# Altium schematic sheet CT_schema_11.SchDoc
size 281 x 153 mm
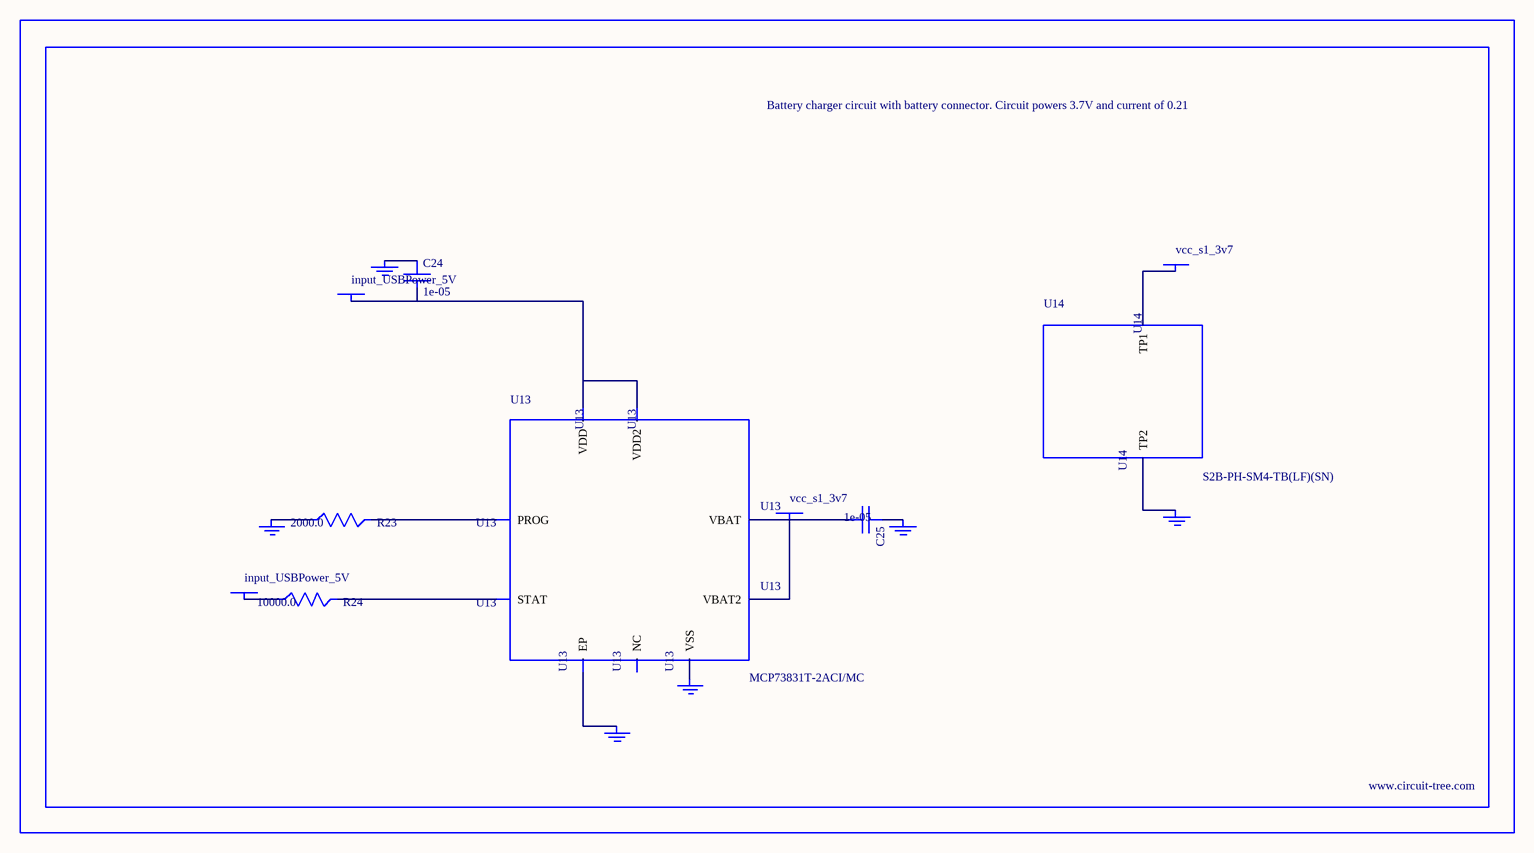
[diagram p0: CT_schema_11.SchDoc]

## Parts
BORDER10  (no value)
C24  1e-05  [C1206]
C25  1e-05  [C1206]
GND_INSTANCE_10_0  (no value)
GND_INSTANCE_10_1  (no value)
GND_INSTANCE_10_2  (no value)
GND_INSTANCE_10_3  (no value)
GND_INSTANCE_10_4  (no value)
GND_INSTANCE_10_5  (no value)
POWER_INSTANCE_10_0  input_USBPower_5V
POWER_INSTANCE_10_1  input_USBPower_5V
POWER_INSTANCE_10_2  vcc_s1_3v7
POWER_INSTANCE_10_3  vcc_s1_3v7
R23  2000.0  [R0603]
R24  10000.0  [R0603]
U13  MCP73831T-2ACI/MC  [DFN8_2X3MC]
U14  S2B-PH-SM4-TB(LF)(SN)  [JST-2-SMD]

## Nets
NetC24_1: C24.1 GND_INSTANCE_10_0.0(GND)
NetC24_2: C24.2 POWER_INSTANCE_10_0.0(PWR) U13.1(VDD) U13.2(VDD2)
NetC25_1: C25.1 GND_INSTANCE_10_1.0(GND)
NetC25_2: C25.2 POWER_INSTANCE_10_2.0(PWR) U13.3(VBAT) U13.4(VBAT2)
NetGND_INSTANCE_10_2_0: GND_INSTANCE_10_2.0(GND) R23.1
NetGND_INSTANCE_10_3_0: GND_INSTANCE_10_3.0(GND) U13.9(EP)
NetGND_INSTANCE_10_4_0: GND_INSTANCE_10_4.0(GND) U13.6(VSS)
NetGND_INSTANCE_10_5_0: GND_INSTANCE_10_5.0(GND) U14.2(TP2)
NetPOWER_INSTANCE_10_1_0: POWER_INSTANCE_10_1.0(PWR) R24.1
NetPOWER_INSTANCE_10_3_0: POWER_INSTANCE_10_3.0(PWR) U14.1(TP1)
NetR23_2: R23.2 U13.8(PROG)
NetR24_2: R24.2 U13.5(STAT)

Not connected (* = marked no-connect by the designer): U13 7(NC)

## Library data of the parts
BORDER10 = BORDER_PAGE10
C24 C25 = C1206C106K3RACTU
GND_INSTANCE_10_0-GND_INSTANCE_10_5 = GND
POWER_INSTANCE_10_0-POWER_INSTANCE_10_3 = PWR
R23 = RC0603JR-072KL
R24 = RC0603JR-0710KL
